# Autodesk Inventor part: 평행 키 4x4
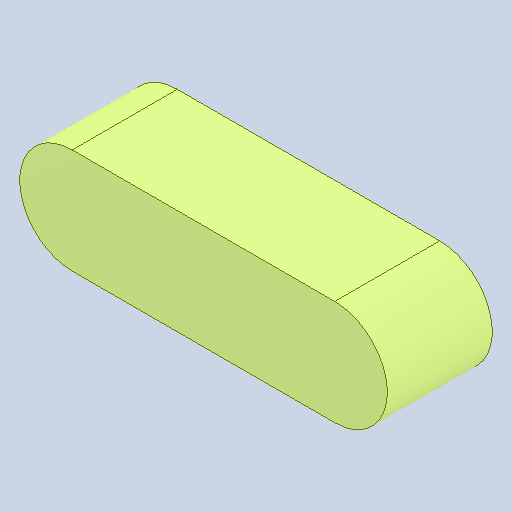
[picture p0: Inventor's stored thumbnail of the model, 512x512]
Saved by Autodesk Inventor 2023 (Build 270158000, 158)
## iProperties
Created: 2025-04
Part Number: 평행 키 4x4
Material: 강철, 연강
Document SubType Name: Modeling
Designer: User
Density: 7.86 g/cm^3
Appearance: 기본값
Author: jhkim
Revision Number: 1
Sending System: Autodesk Inventor 2026
Preprocessor: ST-DEVELOPER v20.1
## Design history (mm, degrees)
feature "솔리드1"
node "솔리드2"
